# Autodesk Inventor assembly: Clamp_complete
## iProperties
Shininess: 64.0
Length Units: 11269
Angle Units: 11279
Time Units: 11290
Mass Units: 11283
Length Display Precision: 3
Angle Display Precision: 2
Compacted: True
Created: 2002-10
Part Number: Clamp_complete
Document SubType Name: Assembly
Designer: roithn
Density: 0.0
Volumn: 0.0
Area: 0.0
PropertySet Name: Model Information
Control State: 0
Master: False
Checked Out: False
Author: roithn
